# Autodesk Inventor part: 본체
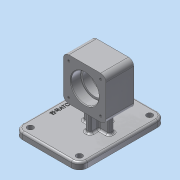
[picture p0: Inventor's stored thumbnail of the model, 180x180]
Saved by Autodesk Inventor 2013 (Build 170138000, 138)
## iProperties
Created: 2020-11
Part Number: 본체
Material: 알루미늄 6061
Document SubType Name: Modeling
Designer: user
Density: 2.71 g/cm^3
Mass: 685.745 g
Surface Area: 542.794 cm^2
Volume: 253.042 cm^3
Author: user
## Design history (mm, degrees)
sketch "스케치1"
  geometry: L1 (-65, -49)-(65, -49); L2 (65, -49)-(65, 49); L3 (65, 49)-(-65, 49); L4 (-65, 49)-(-65, -49); L5 (-65, -49)-(65, 49); L6 (65, -49)-(-65, 49); 1 further point
  constraints: 12 end point, 2 midpoint, 2 parallel, 1 horizontal, 1 perpendicular
  dimensions: "d0" = 130 distance of L3.end L2.end; "d1" = 98 distance of L2.end L1.end
extrude "돌출1" new body sketch "스케치1" distance "d2" = 10; taper "d3" = 0 deg
node "작업 평면2"
sketch "스케치2"
  geometry: L1 (-65, 0)-(-65, 10) reference; L2 (-65, 10)-(65, 10) reference; L3 (65, 10)-(65, 0) reference; L4 (65, 0)-(-65, 0) reference; L5 (21, 38)-(-21, 38); L6 (-21, 38)-(-21, 102); L7 (-21, 102)-(21, 102); L8 (21, 102)-(21, 38); L9 (21, 70)-(-21, 70); 3 further points
  constraints: 10 end point, 4 midpoint, 3 parallel, 1 perpendicular, 1 vertical alignment
  dimensions: "d9" = 64 distance between parallel lines of L5 L7; "d10" = 70 distance between parallel lines of L4 L9; "d11" = 42 distance of L6.end L7.end
extrude "돌출2" join sketch "스케치2" stored distance "d12" = 64; taper "d13" = 0 deg
sketch "스케치3"
  geometry: L1 (-65, 0)-(-65, 10) reference; L2 (-65, 10)-(65, 10) reference; L3 (65, 10)-(65, 0) reference; L4 (65, 0)-(-65, 0) reference; L5 (-21, 38)-(-21, 102) reference; L6 (-21, 102)-(21, 102) reference; L7 (21, 102)-(21, 38) reference; L8 (21, 38)-(-21, 38) reference; L9 (21, 91)-(6.3, 91); L10 (6, 90.7)-(6, 88); L11 (6, 88)-(-6, 88); L12 (-6, 88)-(-6, 90.7); L13 (-6.3, 91)-(-21, 91); L14 (21, 70)-(-21, 70); L15 (-21, 70)-(-21, 91); L16 (21, 91)-(21, 70); A1 r 0.3 centre (6.3, 90.7) between (6.3, 91) and (6, 90.7); A2 r 0.3 centre (-6.3, 90.7) between (-6, 90.7) and (-6.3, 91); 1 further point
  constraints: 16 end point, 4 point on circle, 4 tangent, 3 perpendicular, 2 centre point, 2 collinear, 2 midpoint, 2 parallel, 2 point on line, 1 equal radius
  dimensions: "d14" = 42 diameter of L13 L14; "d16" = 36 diameter of L11 L14; "d17" = 42 diameter of L9 L14; "d19" = 15 distance between parallel lines of L15 L12; "d20" = 0.3 radius of A1; "d21" = 15 distance between parallel lines of L16 L10
revolve "회전1" sketch "스케치3" stored, may be unused: angle "d22" = 90 deg
chamfer "모따기1" distance "d23" = 1; stored, may be unused: second distance "d24" = 2, angle "d25" = 45 deg
fillet "모깎기1" dims "d26" = 8
sketch "스케치4"
  geometry: A1 r 8 centre (8, 48) between (8, 56) and (0, 48) reference; A2 r 8 centre (8, 0) between (0, 0) and (8, -8) reference; A3 r 8 centre (56, 0) between (56, -8) and (64, 0) reference; A4 r 8 centre (56, 48) between (64, 48) and (56, 56) reference; 1 further point
hole "구멍1" sketch "스케치4" at (56, 48), (56, 0), (8, 0), (8, 48) diameter "d27" = 3.242; stored, may be unused: countersink angle "d31" = 90 deg, drill point angle "d33" = 118 deg; dims "d28" = 8, "d29" = 4, "d30" = 2, "d32" = 10
sketch "스케치5"
  geometry: A1 r 8 centre (56, 48) between (64, 48) and (56, 56) reference; A2 r 8 centre (8, 48) between (8, 56) and (0, 48) reference; A3 r 8 centre (8, 0) between (0, 0) and (8, -8) reference; A4 r 8 centre (56, 0) between (56, -8) and (64, 0) reference; 1 further point
hole "구멍2" sketch "스케치5" at (8, 0), (8, 48), (56, 48), (56, 0) diameter "d34" = 3.242; stored, may be unused: countersink angle "d38" = 90 deg, drill point angle "d40" = 118 deg; dims "d35" = 8, "d36" = 4, "d37" = 2, "d39" = 10
fillet "모깎기2" dims "d41" = 12
fillet "모깎기3" dims "d42" = 3
sketch "스케치6"
  geometry: A1 r 9 centre (-53, -37) between (-62, -37) and (-53, -46) reference; A2 r 9 centre (53, -37) between (53, -46) and (62, -37) reference; A3 r 9 centre (53, 37) between (62, 37) and (53, 46) reference; A4 r 9 centre (-53, 37) between (-53, 46) and (-62, 37) reference; 1 further point
hole "구멍3" sketch "스케치6" at (-53, 37), (-53, -37), (53, -37), (53, 37) diameter "d43" = 9; stored, may be unused: countersink angle "d47" = 90 deg, drill point angle "d49" = 118 deg; dims "d44" = 8, "d45" = 4, "d46" = 2, "d48" = 10
sketch "스케치7"
  geometry: L1 (-17, -17)-(-4, -17); L2 (17, -17)-(17, -9); L3 (17, -9)-(4, -9); L4 (-17, -9)-(-17, -17); L5 (-17, -17)-(17, -9); L6 (17, -17)-(-17, -9); L7 (53, 49)-(-53, 49) reference; L8 (-4, -33)-(4, -33); L9 (4, -33)-(4, -17); L10 (4, 7)-(-4, 7); L11 (-4, 7)-(-4, -9); L12 (-4, -33)-(4, 7); L13 (4, -33)-(-4, 7); L14 (-4, -9)-(-4, -17); L15 (-4, -17)-(-4, -33); L16 (-4, -17)-(4, -17); L17 (4, -17)-(17, -17); L18 (4, -9)-(4, 7); L19 (-4, -9)-(-17, -9); L20 (4, -9)-(-4, -9); L21 (4, -17)-(4, -9); 3 further points
  constraints: 40 end point, 20 parallel, 6 perpendicular, 5 midpoint, 4 horizontal, 1 vertical alignment
  dimensions: "d50" = 34 distance of L4.start L2.end; "d51" = 8 distance of L2.end L2.start; "d52" = 62 distance from line of L7 point (0, -13); "d53" = 8 distance of L10.end L10.start; "d54" = 40 distance of L10.start L8.end
extrude "돌출3" join sketch "스케치7" stored distance "d55" = 10; taper "d56" = 0 deg
fillet "모깎기4" dims "d57" = 3
fillet "모깎기5" dims "d58" = 3
sketch "스케치8"
  geometry: L1 (-24.383, 40.013)-(24.383, 40.013); L2 (24.383, 40.013)-(24.383, 37.987); L3 (24.383, 37.987)-(-24.383, 37.987); L4 (-24.383, 37.987)-(-24.383, 40.013); L5 (-24.383, 39)-(24.383, 39); L6 (0, 40.013)-(0, 37.987); L7 (65, -37)-(65, 37) reference; L8 (53, 49)-(-53, 49) reference; 1 further point
  constraints: 4 end point, 4 midpoint, 2 other
  dimensions: "d59" = 65 distance from line of L7 L6.start; "d60" = 10 distance between parallel lines of L5 L8
feature "엠보싱1" sketch "스케치8" dims "d0" = 130, "d1" = 98, "d61" = 0.5, "d62" = 0
node "솔리드1"
node "절단 모서리 투영1"
node "절단 모서리 투영2"
other parameters: "d4" = -13
